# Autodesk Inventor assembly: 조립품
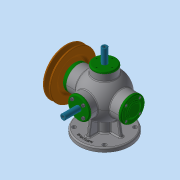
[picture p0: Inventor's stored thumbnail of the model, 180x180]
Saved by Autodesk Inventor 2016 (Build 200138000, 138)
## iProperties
Created: 2019-11
Part Number: 조립품
Material: 일반
Document SubType Name: Assembly
Designer: user
Author: user
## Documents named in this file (17)
- C:\Users\user\Desktop\391120V1001\조립품.iam
- C:\Users\user\Desktop\391120V1001\V-벨트풀리.ipt
- C:\Users\user\Desktop\391120V1001\너트 M8x1.ipt
- C:\Users\user\Desktop\391120V1001\뒤커버.ipt
- C:\Users\user\Desktop\391120V1001\베어링 6202.ipt
- C:\Users\user\Desktop\391120V1001\본체.ipt
- C:\Users\user\Desktop\391120V1001\본체커버.ipt
- C:\Users\user\Desktop\391120V1001\볼트 M4.ipt
- C:\Users\user\Desktop\391120V1001\스프링1.ipt
- C:\Users\user\Desktop\391120V1001\스프링2.ipt
- C:\Users\user\Desktop\391120V1001\슬라이드 커버.ipt
- C:\Users\user\Desktop\391120V1001\슬라이드.ipt
- C:\Users\user\Desktop\391120V1001\앞커버.ipt
- C:\Users\user\Desktop\391120V1001\오일 실.ipt
- C:\Users\user\Desktop\391120V1001\와셔 8x17.ipt
- C:\Users\user\Desktop\391120V1001\축.ipt
- C:\Users\user\Desktop\391120V1001\키 4x4.ipt
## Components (1 placed, 1 different names)
1. V-벨트풀리:1
